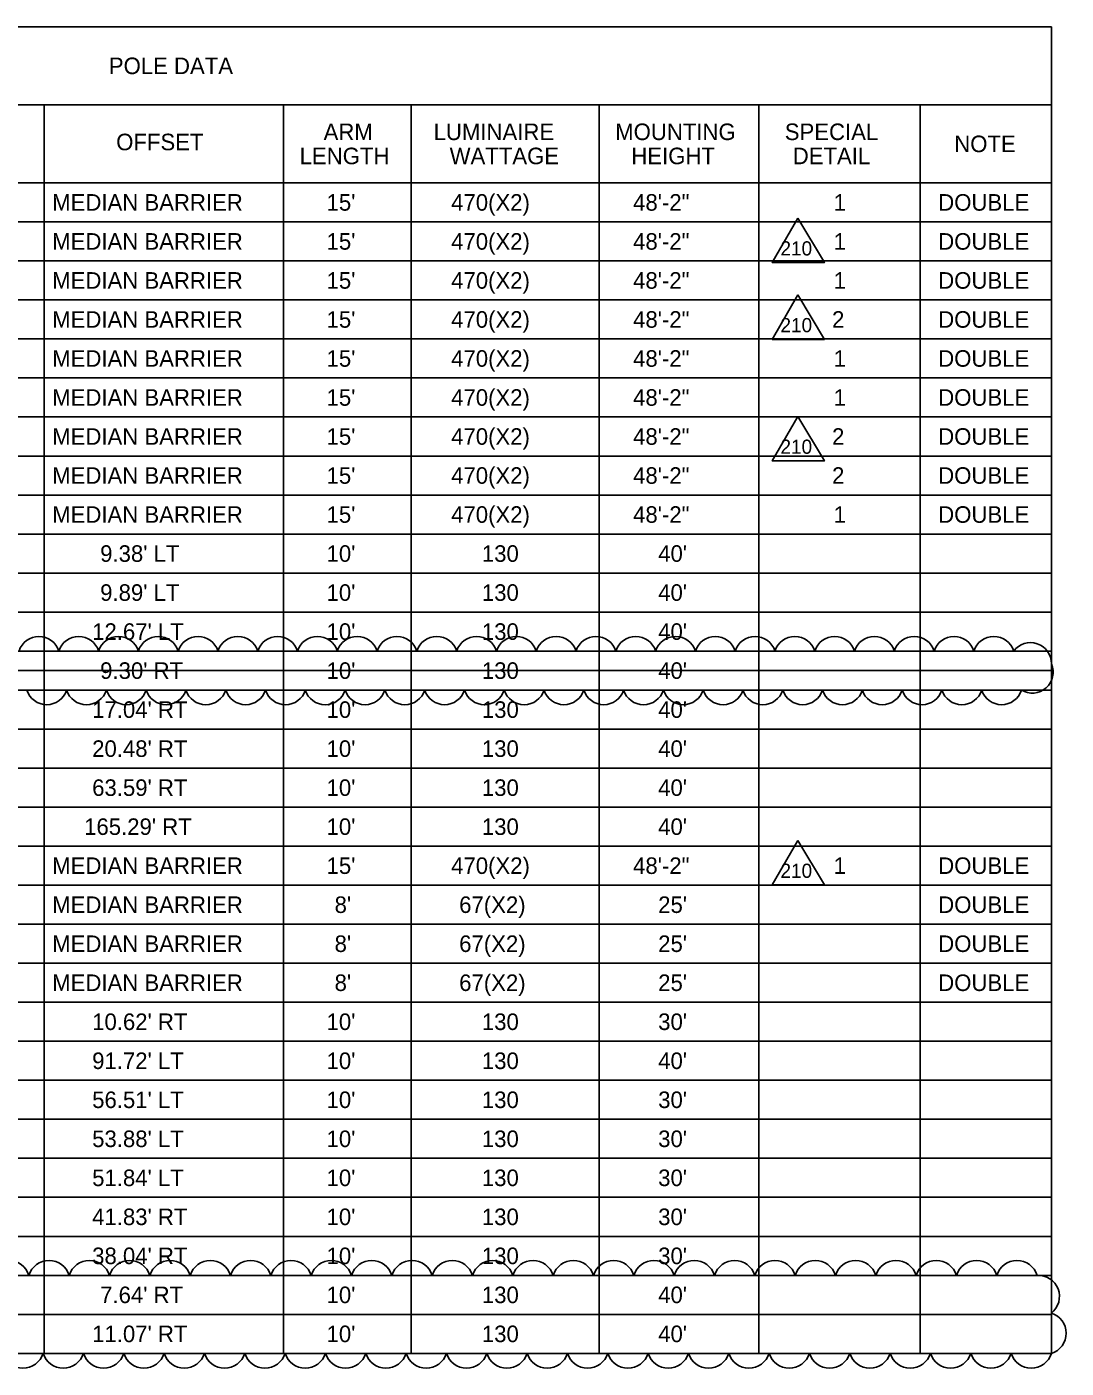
# Model space of a CAD drawing. Extents: x -816.7 to -800.7, y -2197.9 to -2187.9.
# Drawn here: x -805.1 to -800.71, y -2193.53 to -2187.86 of the extents above; entities that cross this region are included whole.
import ezdxf

# ---------------------------------------------------------------- set-up
doc = ezdxf.new("R2010")
doc.units = 0
for name, color, linetype in [('Cloud_dp', 7, 'Continuous'), ('NonPlottingEle_dp', 7, 'Continuous'), ('SumBoxBorder_dp', 7, 'Continuous'), ('SumBoxLines_dp', 7, 'Continuous'), ('SumBoxLinesMin_dp', 7, 'Continuous'), ('TextLabel', 7, 'Continuous')]:
    doc.layers.add(name, color=color, linetype=linetype)

msp = doc.modelspace()

# ---------------------------------------------------------------- linework, layer by layer
at = {"layer": 'Cloud_dp'}
msp.add_line((-808.1636, -2190.5787), (-800.7686, -2190.5787), dxfattribs=at)
for points in [[(-801.8411, -2188.6653), (-801.9488, -2188.8534), (-801.7282, -2188.8534)], [(-801.8411, -2188.9897), (-801.9488, -2189.1778), (-801.7282, -2189.1778)], [(-801.8411, -2189.504), (-801.9488, -2189.6921), (-801.7282, -2189.6921)], [(-801.8411, -2191.2972), (-801.9488, -2191.4853), (-801.7282, -2191.4853)]]:
    msp.add_lwpolyline(points, close=True, dxfattribs=at)
for centre, radius, start, end in [((-805.0506, -2190.5227), 0.0882, 17.5, 162.5), ((-804.8823, -2190.5227), 0.0882, 17.5, 162.5), ((-804.7141, -2190.5227), 0.0882, 17.5, 162.5), ((-804.5458, -2190.5227), 0.0882, 17.5, 162.5), ((-804.3775, -2190.5227), 0.0882, 17.5, 162.5), ((-804.2093, -2190.5227), 0.0882, 17.5, 162.5), ((-804.041, -2190.5227), 0.0882, 17.5, 162.5), ((-803.8727, -2190.5227), 0.0882, 17.5, 162.5), ((-803.7045, -2190.5227), 0.0882, 17.5, 162.5), ((-803.5362, -2190.5227), 0.0882, 17.5, 162.5), ((-803.3679, -2190.5227), 0.0882, 17.5, 162.5), ((-803.1996, -2190.5227), 0.0882, 17.5, 162.5), ((-803.0314, -2190.5227), 0.0882, 17.5, 162.5), ((-802.8631, -2190.5227), 0.0882, 17.5, 162.5), ((-802.6948, -2190.5227), 0.0882, 17.5, 162.5), ((-802.5266, -2190.5227), 0.0882, 17.5, 162.5), ((-802.3583, -2190.5227), 0.0882, 17.5, 162.5), ((-802.19, -2190.5227), 0.0882, 17.5, 162.5), ((-802.0218, -2190.5227), 0.0882, 17.5, 162.5), ((-801.8535, -2190.5227), 0.0882, 17.5, 162.5), ((-801.6852, -2190.5227), 0.0882, 17.5, 162.5), ((-801.517, -2190.5227), 0.0882, 17.5, 162.5), ((-801.3487, -2190.5227), 0.0882, 17.5, 162.5), ((-801.1804, -2190.5227), 0.0882, 17.5, 162.5), ((-801.0122, -2190.5227), 0.0882, 17.5, 162.5), ((-800.8568, -2190.5485), 0.0883, 358.7167, 143.7167), ((-800.8493, -2190.5859), 0.0881, 238.7137, 23.7137), ((-805.0176, -2190.6347), 0.0882, 197.5, 342.5), ((-804.8494, -2190.6347), 0.0882, 197.5, 342.5), ((-804.6811, -2190.6347), 0.0882, 197.5, 342.5), ((-804.5128, -2190.6347), 0.0882, 197.5, 342.5), ((-804.3446, -2190.6347), 0.0882, 197.5, 342.5), ((-804.1763, -2190.6347), 0.0882, 197.5, 342.5), ((-804.008, -2190.6347), 0.0882, 197.5, 342.5), ((-803.8398, -2190.6347), 0.0882, 197.5, 342.5), ((-803.6715, -2190.6347), 0.0882, 197.5, 342.5), ((-803.5032, -2190.6347), 0.0882, 197.5, 342.5), ((-803.3349, -2190.6347), 0.0882, 197.5, 342.5), ((-803.1667, -2190.6347), 0.0882, 197.5, 342.5), ((-802.9984, -2190.6347), 0.0882, 197.5, 342.5), ((-802.8301, -2190.6347), 0.0882, 197.5, 342.5), ((-802.6619, -2190.6347), 0.0882, 197.5, 342.5), ((-802.4936, -2190.6347), 0.0882, 197.5, 342.5), ((-802.3253, -2190.6347), 0.0882, 197.5, 342.5), ((-802.1571, -2190.6347), 0.0882, 197.5, 342.5), ((-801.9888, -2190.6347), 0.0882, 197.5, 342.5), ((-801.8205, -2190.6347), 0.0882, 197.5, 342.5), ((-801.6523, -2190.6347), 0.0882, 197.5, 342.5), ((-801.484, -2190.6347), 0.0882, 197.5, 342.5), ((-801.3157, -2190.6347), 0.0882, 197.5, 342.5), ((-801.1475, -2190.6347), 0.0882, 197.5, 342.5), ((-800.9792, -2190.6347), 0.0882, 197.5, 342.5), ((-805.1785, -2193.1631), 0.0894, 17.5, 162.5), ((-805.0079, -2193.1631), 0.0894, 17.5, 162.5), ((-804.8374, -2193.1631), 0.0894, 17.5, 162.5), ((-804.6668, -2193.1631), 0.0894, 17.5, 162.5), ((-804.4962, -2193.1631), 0.0894, 17.5, 162.5), ((-804.3256, -2193.1631), 0.0894, 17.5, 162.5), ((-804.1551, -2193.1631), 0.0894, 17.5, 162.5), ((-803.9845, -2193.1631), 0.0894, 17.5, 162.5), ((-803.8139, -2193.1631), 0.0894, 17.5, 162.5), ((-803.6433, -2193.1631), 0.0894, 17.5, 162.5), ((-803.4727, -2193.1631), 0.0894, 17.5, 162.5), ((-803.3022, -2193.1631), 0.0894, 17.5, 162.5), ((-803.1316, -2193.1631), 0.0894, 17.5, 162.5), ((-802.961, -2193.1631), 0.0894, 17.5, 162.5), ((-802.7904, -2193.1631), 0.0894, 17.5, 162.5), ((-802.6199, -2193.1631), 0.0894, 17.5, 162.5), ((-802.4493, -2193.1631), 0.0894, 17.5, 162.5), ((-802.2787, -2193.1631), 0.0894, 17.5, 162.5), ((-802.1081, -2193.1631), 0.0894, 17.5, 162.5), ((-801.9376, -2193.1631), 0.0894, 17.5, 162.5), ((-801.767, -2193.1631), 0.0894, 17.5, 162.5), ((-801.5964, -2193.1631), 0.0894, 17.5, 162.5), ((-801.4258, -2193.1631), 0.0894, 17.5, 162.5), ((-801.2553, -2193.1631), 0.0894, 17.5, 162.5), ((-801.0847, -2193.1631), 0.0894, 17.5, 162.5), ((-800.9141, -2193.1631), 0.0894, 17.5, 162.5), ((-800.8238, -2193.2254), 0.0894, 308.2038, 93.2038), ((-800.7955, -2193.3809), 0.0894, 287.5, 72.5), ((-805.1183, -2193.4393), 0.0894, 197.5, 342.5), ((-804.9477, -2193.4393), 0.0894, 197.5, 342.5), ((-804.7771, -2193.4393), 0.0894, 197.5, 342.5), ((-804.6065, -2193.4393), 0.0894, 197.5, 342.5), ((-804.4359, -2193.4393), 0.0894, 197.5, 342.5), ((-804.2654, -2193.4393), 0.0894, 197.5, 342.5), ((-804.0948, -2193.4393), 0.0894, 197.5, 342.5), ((-803.9242, -2193.4393), 0.0894, 197.5, 342.5), ((-803.7536, -2193.4393), 0.0894, 197.5, 342.5), ((-803.5831, -2193.4393), 0.0894, 197.5, 342.5), ((-803.4125, -2193.4393), 0.0894, 197.5, 342.5), ((-803.2419, -2193.4393), 0.0894, 197.5, 342.5), ((-803.0713, -2193.4393), 0.0894, 197.5, 342.5), ((-802.9008, -2193.4393), 0.0894, 197.5, 342.5), ((-802.7302, -2193.4393), 0.0894, 197.5, 342.5), ((-802.5596, -2193.4393), 0.0894, 197.5, 342.5), ((-802.389, -2193.4393), 0.0894, 197.5, 342.5), ((-802.2185, -2193.4393), 0.0894, 197.5, 342.5), ((-802.0479, -2193.4393), 0.0894, 197.5, 342.5), ((-801.8773, -2193.4393), 0.0894, 197.5, 342.5), ((-801.7067, -2193.4393), 0.0894, 197.5, 342.5), ((-801.5362, -2193.4393), 0.0894, 197.5, 342.5), ((-801.3656, -2193.4393), 0.0894, 197.5, 342.5), ((-801.195, -2193.4393), 0.0894, 197.5, 342.5), ((-801.0244, -2193.4393), 0.0894, 197.5, 342.5), ((-800.8539, -2193.4393), 0.0894, 197.5, 342.5)]:
    msp.add_arc(centre, radius, start, end, dxfattribs=at)
at = {"layer": 'NonPlottingEle_dp'}
for points in [[(-808.1636, -2190.4962), (-800.7686, -2190.4962), (-800.7686, -2190.6612), (-808.1636, -2190.6612)], [(-808.1636, -2193.1362), (-800.7686, -2193.1362), (-800.7686, -2193.4662), (-808.1636, -2193.4662)]]:
    msp.add_lwpolyline(points, close=True, dxfattribs=at)
at = {"layer": 'SumBoxBorder_dp'}
for p, q in [((-808.1636, -2187.8562), (-800.7686, -2187.8562)), ((-800.7686, -2187.8562), (-800.7686, -2193.4662)), ((-808.1636, -2188.1862), (-800.7686, -2188.1862)), ((-808.1636, -2188.1862), (-800.7686, -2188.1862)), ((-808.1636, -2193.4662), (-800.7686, -2193.4662)), ((-808.1636, -2193.4662), (-800.7686, -2193.4662))]:
    msp.add_line(p, q, dxfattribs=at)
at = {"layer": 'SumBoxLines_dp'}
for p, q in [((-805.0286, -2188.1862), (-805.0286, -2191.4862)), ((-805.0286, -2188.1862), (-805.0286, -2193.4662)), ((-804.0161, -2188.1862), (-804.0161, -2193.4662)), ((-804.0161, -2188.1862), (-804.0161, -2193.4662)), ((-803.4761, -2188.1862), (-803.4761, -2191.9812)), ((-803.4761, -2188.1862), (-803.4761, -2193.4662)), ((-802.6811, -2188.1862), (-802.6811, -2193.4662)), ((-802.6811, -2188.1862), (-802.6811, -2193.4662)), ((-802.0061, -2188.1862), (-802.0061, -2193.4662)), ((-802.0061, -2188.1862), (-802.0061, -2193.4662)), ((-801.3236, -2188.1862), (-801.3236, -2193.4662)), ((-808.1636, -2188.5162), (-800.7686, -2188.5162)), ((-805.0286, -2191.6512), (-805.0286, -2193.4662)), ((-803.4761, -2192.1462), (-803.4761, -2193.4662))]:
    msp.add_line(p, q, dxfattribs=at)
at = {"layer": 'SumBoxLinesMin_dp'}
for p, q in [((-808.1636, -2188.5162), (-800.7686, -2188.5162)), ((-808.1636, -2188.6812), (-800.7686, -2188.6812)), ((-808.1636, -2188.6812), (-800.7686, -2188.6812)), ((-808.1636, -2188.8462), (-800.7686, -2188.8462)), ((-808.1636, -2188.8462), (-800.7686, -2188.8462)), ((-808.1636, -2189.0112), (-800.7686, -2189.0112)), ((-808.1636, -2189.0112), (-800.7686, -2189.0112)), ((-808.1636, -2189.1762), (-800.7686, -2189.1762)), ((-808.1636, -2189.1762), (-800.7686, -2189.1762)), ((-808.1636, -2189.3412), (-800.7686, -2189.3412)), ((-808.1636, -2189.3412), (-800.7686, -2189.3412)), ((-808.1636, -2189.5062), (-800.7686, -2189.5062)), ((-808.1636, -2189.5062), (-800.7686, -2189.5062)), ((-808.1636, -2189.6712), (-800.7686, -2189.6712)), ((-808.1636, -2189.6712), (-800.7686, -2189.6712)), ((-808.1636, -2189.8362), (-800.7686, -2189.8362)), ((-808.1636, -2189.8362), (-800.7686, -2189.8362)), ((-808.1636, -2190.0012), (-800.7686, -2190.0012)), ((-808.1636, -2190.0012), (-800.7686, -2190.0012)), ((-808.1636, -2190.1662), (-800.7686, -2190.1662)), ((-808.1636, -2190.1662), (-800.7686, -2190.1662)), ((-808.1636, -2190.3312), (-800.7686, -2190.3312)), ((-808.1636, -2190.3312), (-800.7686, -2190.3312)), ((-808.1636, -2190.4962), (-800.7686, -2190.4962)), ((-808.1636, -2190.4962), (-800.7686, -2190.4962)), ((-808.1636, -2190.6612), (-800.7686, -2190.6612)), ((-808.1636, -2190.6612), (-800.7686, -2190.6612)), ((-808.1636, -2190.8262), (-800.7686, -2190.8262)), ((-808.1636, -2190.8262), (-800.7686, -2190.8262)), ((-808.1636, -2190.9912), (-800.7686, -2190.9912)), ((-808.1636, -2190.9912), (-800.7686, -2190.9912)), ((-808.1636, -2191.1562), (-800.7686, -2191.1562)), ((-808.1636, -2191.1562), (-800.7686, -2191.1562)), ((-808.1636, -2191.3212), (-800.7686, -2191.3212)), ((-808.1636, -2191.3212), (-800.7686, -2191.3212)), ((-808.1636, -2191.4862), (-800.7686, -2191.4862)), ((-808.1636, -2191.4862), (-800.7686, -2191.4862)), ((-808.1636, -2191.6512), (-800.7686, -2191.6512)), ((-805.0286, -2191.6512), (-800.7686, -2191.6512)), ((-808.1636, -2191.8162), (-800.7686, -2191.8162)), ((-808.1636, -2191.8162), (-800.7686, -2191.8162)), ((-808.1636, -2191.9812), (-800.7686, -2191.9812)), ((-808.1636, -2191.9812), (-800.7686, -2191.9812)), ((-808.1636, -2192.1462), (-800.7686, -2192.1462)), ((-807.2786, -2192.1462), (-804.0161, -2192.1462)), ((-803.4761, -2192.1462), (-800.7686, -2192.1462)), ((-808.1636, -2192.3112), (-800.7686, -2192.3112)), ((-808.1636, -2192.3112), (-800.7686, -2192.3112)), ((-808.1636, -2192.4762), (-800.7686, -2192.4762)), ((-805.0286, -2192.4762), (-800.7686, -2192.4762)), ((-808.1636, -2192.6412), (-800.7686, -2192.6412)), ((-808.1636, -2192.6412), (-800.7686, -2192.6412)), ((-808.1636, -2192.8062), (-800.7686, -2192.8062)), ((-805.0286, -2192.8062), (-800.7686, -2192.8062)), ((-808.1636, -2192.9712), (-800.7686, -2192.9712)), ((-808.1636, -2192.9712), (-800.7686, -2192.9712)), ((-808.1636, -2193.1362), (-800.7686, -2193.1362)), ((-808.1636, -2193.1362), (-800.7686, -2193.1362)), ((-808.1636, -2193.3012), (-800.7686, -2193.3012)), ((-808.1636, -2193.3012), (-800.7686, -2193.3012))]:
    msp.add_line(p, q, dxfattribs=at)

# ---------------------------------------------------------------- texts
at = {"layer": 'Cloud_dp'}
for p in [(-801.9143, -2188.8232), (-801.9143, -2189.1477), (-801.9143, -2189.6619), (-801.9143, -2191.4552)]:
    msp.add_text('210', height=0.05998, rotation=0, dxfattribs=at).set_placement(p)
at = {"layer": 'TextLabel'}
for s, p in [('POLE DATA', (-804.755, -2188.0562)), ('ARM', (-803.8466, -2188.3352)), ('LUMINAIRE', (-803.3813, -2188.3352)), ('MOUNTING', (-802.6133, -2188.3352)), ('SPECIAL', (-801.8962, -2188.3352)), ('OFFSET', (-804.7238, -2188.3782)), ('NOTE', (-801.1794, -2188.3862)), ('LENGTH', (-803.948, -2188.4372)), ('WATTAGE', (-803.3135, -2188.4372)), ('HEIGHT', (-802.5451, -2188.4372)), ('DETAIL', (-801.8624, -2188.4372)), ('MEDIAN BARRIER', (-804.9944, -2188.6337)), ("15'", (-803.834, -2188.6337)), ('470(X2)', (-803.3071, -2188.6337)), ('48\'-2"', (-802.5376, -2188.6337)), ('1', (-801.6895, -2188.6337)), ('DOUBLE', (-801.2471, -2188.6337)), ('MEDIAN BARRIER', (-804.9944, -2188.7987)), ("15'", (-803.834, -2188.7987)), ('470(X2)', (-803.3071, -2188.7987)), ('48\'-2"', (-802.5376, -2188.7987)), ('1', (-801.6895, -2188.7987)), ('DOUBLE', (-801.2471, -2188.7987)), ('MEDIAN BARRIER', (-804.9944, -2188.9637)), ("15'", (-803.834, -2188.9637)), ('470(X2)', (-803.3071, -2188.9637)), ('48\'-2"', (-802.5376, -2188.9637)), ('1', (-801.6895, -2188.9637)), ('DOUBLE', (-801.2471, -2188.9637)), ('MEDIAN BARRIER', (-804.9944, -2189.1287)), ("15'", (-803.834, -2189.1287)), ('470(X2)', (-803.3071, -2189.1287)), ('48\'-2"', (-802.5376, -2189.1287)), ('2', (-801.6962, -2189.1287)), ('DOUBLE', (-801.2471, -2189.1287)), ('MEDIAN BARRIER', (-804.9944, -2189.2937)), ("15'", (-803.834, -2189.2937)), ('470(X2)', (-803.3071, -2189.2937)), ('48\'-2"', (-802.5376, -2189.2937)), ('1', (-801.6895, -2189.2937)), ('DOUBLE', (-801.2471, -2189.2937)), ('MEDIAN BARRIER', (-804.9944, -2189.4587)), ("15'", (-803.834, -2189.4587)), ('470(X2)', (-803.3071, -2189.4587)), ('48\'-2"', (-802.5376, -2189.4587)), ('1', (-801.6895, -2189.4587)), ('DOUBLE', (-801.2471, -2189.4587)), ('MEDIAN BARRIER', (-804.9944, -2189.6237)), ("15'", (-803.834, -2189.6237)), ('470(X2)', (-803.3071, -2189.6237)), ('48\'-2"', (-802.5376, -2189.6237)), ('2', (-801.6962, -2189.6237)), ('DOUBLE', (-801.2471, -2189.6237)), ('MEDIAN BARRIER', (-804.9944, -2189.7887)), ("15'", (-803.834, -2189.7887)), ('470(X2)', (-803.3071, -2189.7887)), ('48\'-2"', (-802.5376, -2189.7887)), ('2', (-801.6962, -2189.7887)), ('DOUBLE', (-801.2471, -2189.7887)), ('470(X2)', (-803.3071, -2189.9537)), ('MEDIAN BARRIER', (-804.9944, -2189.9537)), ("15'", (-803.834, -2189.9537)), ('48\'-2"', (-802.5376, -2189.9537)), ('1', (-801.6895, -2189.9537)), ('DOUBLE', (-801.2471, -2189.9537)), ("9.38' LT", (-804.7916, -2190.1187)), ("10'", (-803.834, -2190.1187)), ('130', (-803.1772, -2190.1187)), ("40'", (-802.4315, -2190.1187)), ("9.89' LT", (-804.7916, -2190.2837)), ("10'", (-803.834, -2190.2837)), ('130', (-803.1772, -2190.2837)), ("40'", (-802.4315, -2190.2837)), ("12.67' LT", (-804.8254, -2190.4487)), ("10'", (-803.834, -2190.4487)), ('130', (-803.1772, -2190.4487)), ("40'", (-802.4315, -2190.4487)), ("9.30' RT", (-804.7916, -2190.6137)), ("10'", (-803.834, -2190.6137)), ('130', (-803.1772, -2190.6137)), ("40'", (-802.4315, -2190.6137)), ("17.04' RT", (-804.8254, -2190.7787)), ("10'", (-803.834, -2190.7787)), ('130', (-803.1772, -2190.7787)), ("40'", (-802.4315, -2190.7787)), ("20.48' RT", (-804.8254, -2190.9437)), ("10'", (-803.834, -2190.9437)), ('130', (-803.1772, -2190.9437)), ("40'", (-802.4315, -2190.9437)), ("63.59' RT", (-804.8254, -2191.1087)), ("10'", (-803.834, -2191.1087)), ('130', (-803.1772, -2191.1087)), ("40'", (-802.4315, -2191.1087)), ("165.29' RT", (-804.8593, -2191.2737)), ("10'", (-803.834, -2191.2737)), ('130', (-803.1772, -2191.2737)), ("40'", (-802.4315, -2191.2737)), ('MEDIAN BARRIER', (-804.9944, -2191.4387)), ("15'", (-803.834, -2191.4387)), ('470(X2)', (-803.3071, -2191.4387)), ('48\'-2"', (-802.5376, -2191.4387)), ('1', (-801.6895, -2191.4387)), ('DOUBLE', (-801.2471, -2191.4387)), ('MEDIAN BARRIER', (-804.9944, -2191.6037)), ("8'", (-803.8001, -2191.6037)), ('67(X2)', (-803.2732, -2191.6037)), ("25'", (-802.4315, -2191.6037)), ('DOUBLE', (-801.2471, -2191.6037)), ('67(X2)', (-803.2732, -2191.7687)), ('MEDIAN BARRIER', (-804.9944, -2191.7687)), ("8'", (-803.8001, -2191.7687)), ("25'", (-802.4315, -2191.7687)), ('DOUBLE', (-801.2471, -2191.7687)), ('MEDIAN BARRIER', (-804.9944, -2191.9337)), ("8'", (-803.8001, -2191.9337)), ('67(X2)', (-803.2732, -2191.9337)), ("25'", (-802.4315, -2191.9337)), ('DOUBLE', (-801.2471, -2191.9337)), ("10.62' RT", (-804.8254, -2192.0987)), ("10'", (-803.834, -2192.0987)), ('130', (-803.1772, -2192.0987)), ("30'", (-802.4315, -2192.0987)), ("91.72' LT", (-804.8254, -2192.2637)), ("10'", (-803.834, -2192.2637)), ('130', (-803.1772, -2192.2637)), ("40'", (-802.4315, -2192.2637)), ("56.51' LT", (-804.8254, -2192.4287)), ("10'", (-803.834, -2192.4287)), ('130', (-803.1772, -2192.4287)), ("30'", (-802.4315, -2192.4287)), ("53.88' LT", (-804.8254, -2192.5937)), ("10'", (-803.834, -2192.5937)), ('130', (-803.1772, -2192.5937)), ("30'", (-802.4315, -2192.5937)), ("51.84' LT", (-804.8254, -2192.7587)), ("10'", (-803.834, -2192.7587)), ('130', (-803.1772, -2192.7587)), ("30'", (-802.4315, -2192.7587)), ("41.83' RT", (-804.8254, -2192.9237)), ("10'", (-803.834, -2192.9237)), ('130', (-803.1772, -2192.9237)), ("30'", (-802.4315, -2192.9237)), ("38.04' RT", (-804.8254, -2193.0887)), ("10'", (-803.834, -2193.0887)), ('130', (-803.1772, -2193.0887)), ("30'", (-802.4315, -2193.0887)), ("7.64' RT", (-804.7916, -2193.2537)), ("10'", (-803.834, -2193.2537)), ('130', (-803.1772, -2193.2537)), ("40'", (-802.4315, -2193.2537)), ("11.07' RT", (-804.8254, -2193.4187)), ("10'", (-803.834, -2193.4187)), ('130', (-803.1772, -2193.4187)), ("40'", (-802.4315, -2193.4187))]:
    msp.add_text(s, height=0.07, dxfattribs=at).set_placement(p)

doc.saveas('drawing.dxf')
